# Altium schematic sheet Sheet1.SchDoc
size A3
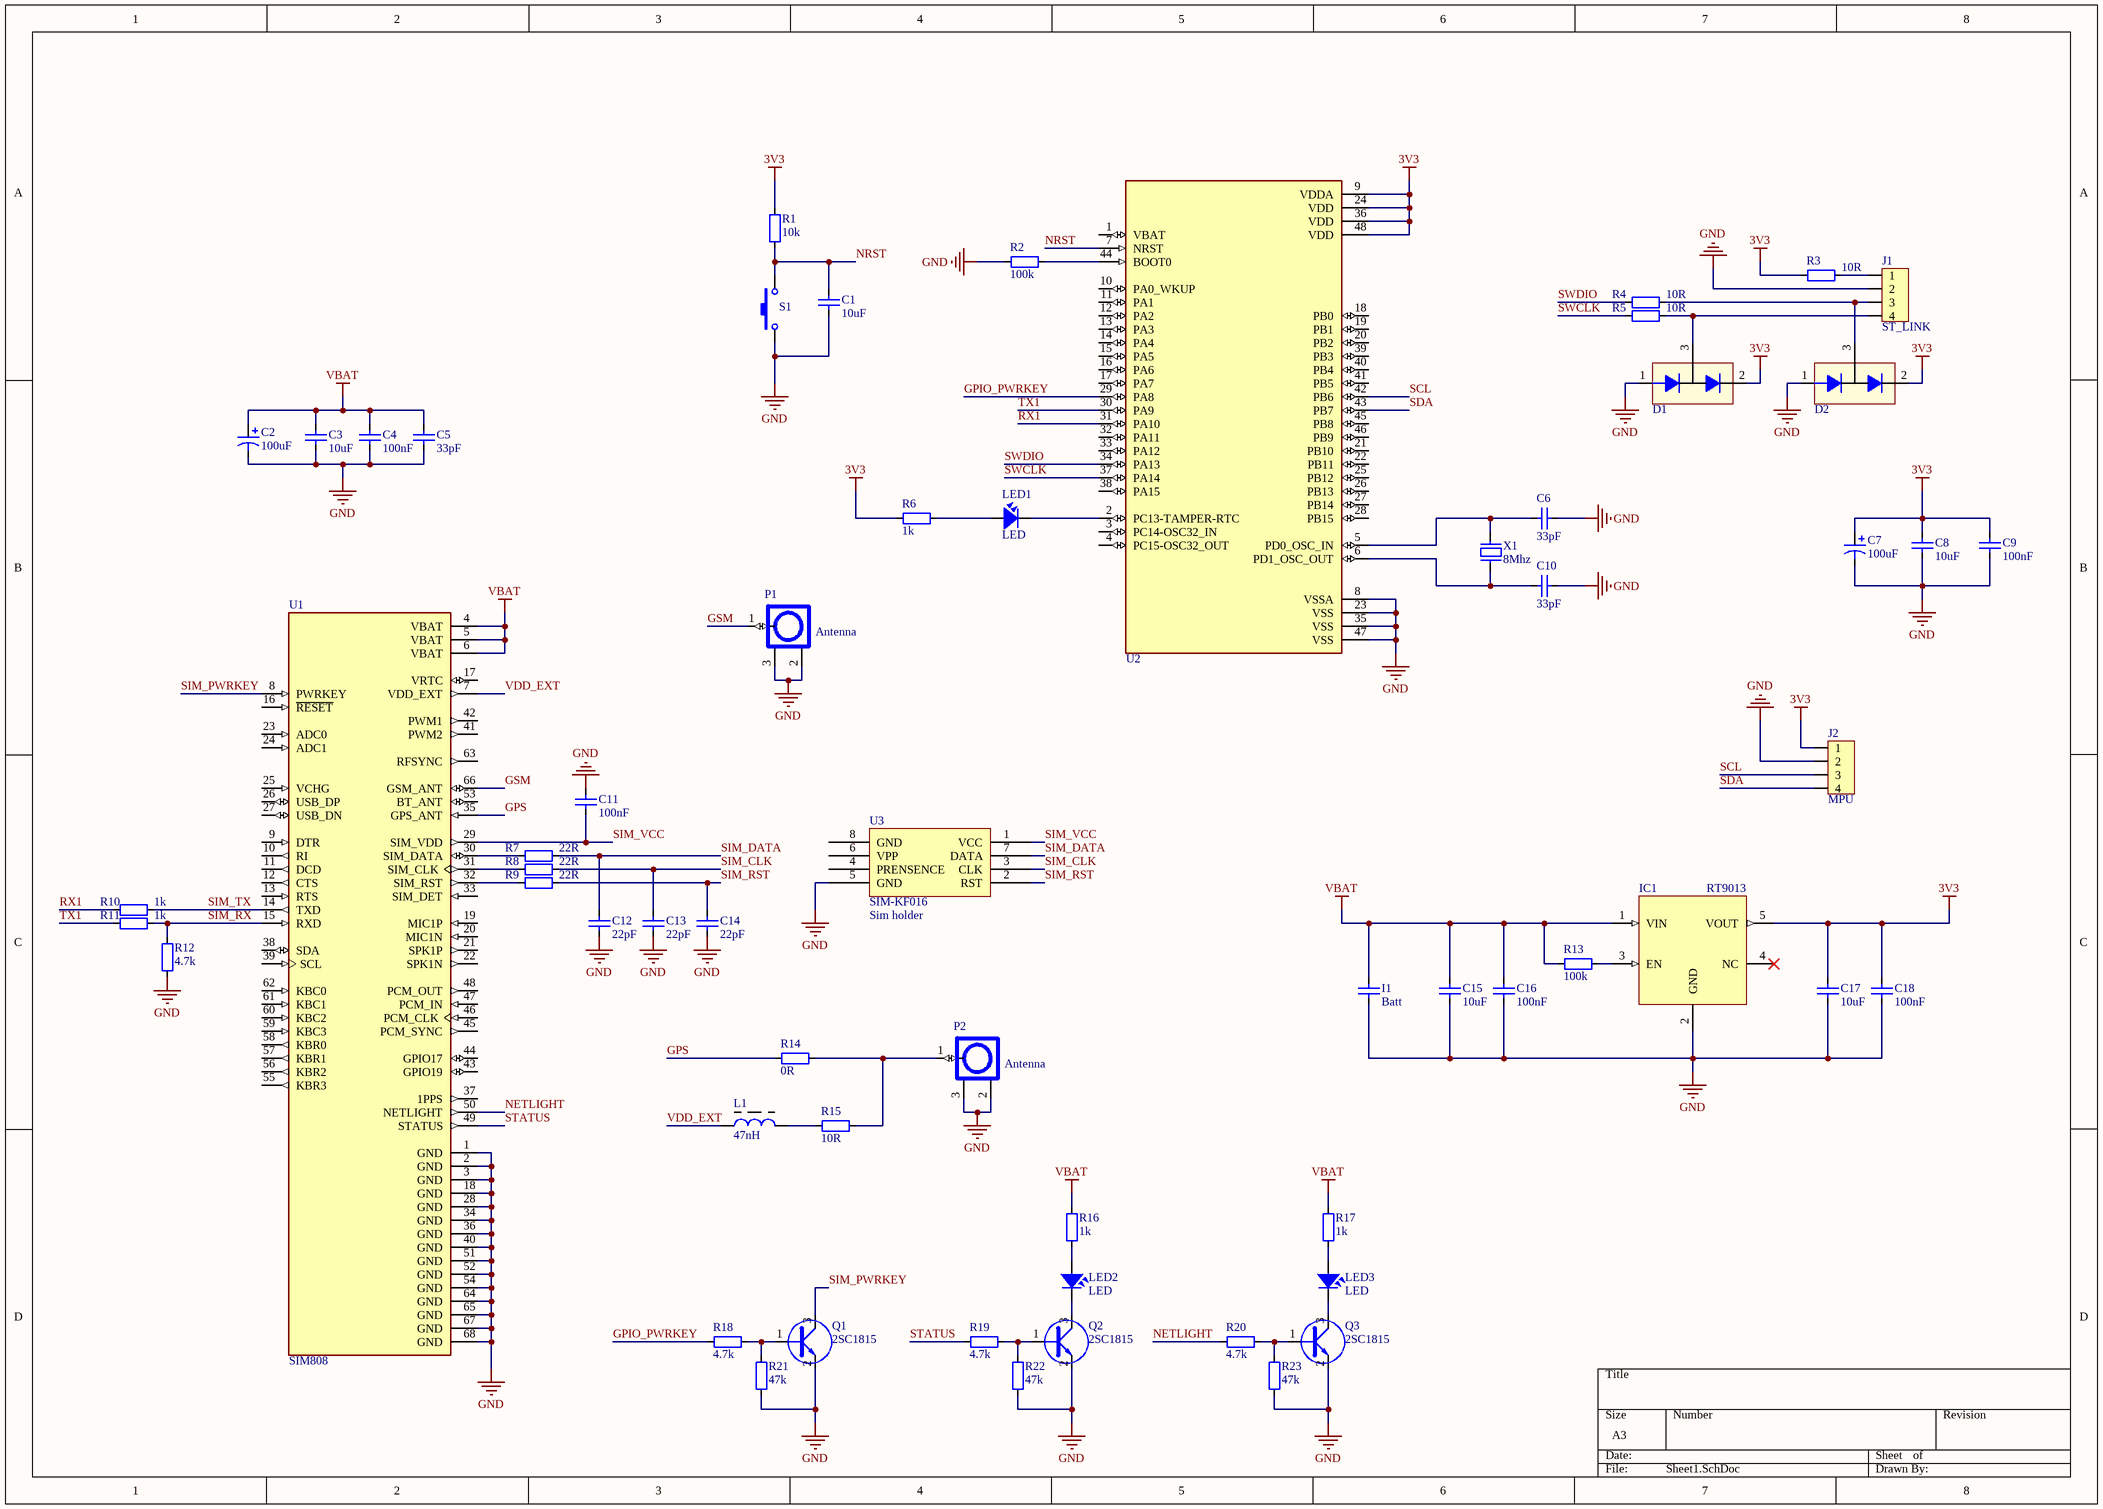
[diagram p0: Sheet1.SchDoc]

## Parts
C1  10uF  [CAP_0603]
C2  100uF  [CAP_7343]
C3  10uF  [CAP_0603]
C4  100nF  [CAP_0603]
C5  33pF  [CAP_0603]
C6  33pF  [CAP_0603]
C7  100uF  [CAP_7343]
C8  10uF  [CAP_0603]
C9  100nF  [CAP_0603]
C10  33pF  [CAP_0603]
C11  100nF  [CAP_0603]
C12  22pF  [CAP_0603]
C13  22pF  [CAP_0603]
C14  22pF  [CAP_0603]
C15  10uF  [CAP_0603]
C16  100nF  [CAP_0603]
C17  10uF  [CAP_0603]
C18  100nF  [CAP_0603]
D1  DIODE-BAV99  [SOT23]  (value not drawn)
D2  DIODE-BAV99  [SOT23]  (value not drawn)
I1  Batt  [CAP_3216]
IC1  RT9013  [SOT23-5]
J1  ST_LINK  [JP4-D1T]
J2  MPU  [JP4-D1T]
L1  47nH  [L-0805]
LED1  LED  [LED-0805-Orange]
LED2  LED  [LED-0805-Yellow]
LED3  LED  [LED-0805-Red]
P1  Antenna  [IPXS]
P2  Antenna  [IPXS]
Q1  2SC1815  [SOT23D]
Q2  2SC1815  [SOT23D]
Q3  2SC1815  [SOT23D]
R1  10k  [RES-SMD-0603]
R2  100k  [RES-SMD-0603]
R3  10R  [RES-SMD-0603]
R4  10R  [RES-SMD-0603]
R5  10R  [RES-SMD-0603]
R6  1k  [RES-SMD-0603]
R7  22R  [RES-SMD-0603]
R8  22R  [RES-SMD-0603]
R9  22R  [RES-SMD-0603]
R10  1k  [RES-SMD-0603]
R11  1k  [RES-SMD-0603]
R12  4.7k  [RES-SMD-0603]
R13  100k  [RES-SMD-0603]
R14  0R  [RES-SMD-0805]
R15  10R  [RES-SMD-0805]
R16  1k  [RES-SMD-0603]
R17  1k  [RES-SMD-0603]
R18  4.7k  [RES-SMD-0603]
R19  4.7k  [RES-SMD-0603]
R20  4.7k  [RES-SMD-0603]
R21  47k  [RES-SMD-0603]
R22  47k  [RES-SMD-0603]
R23  47k  [RES-SMD-0603]
S1  SW-SMD  [SW 3x2x4]  (value not drawn)
U1  SIM808  [XCVR_SIM808]
U2  STM32  [LQFP 48]  (value not drawn)
U3  SIM-KF016  value Sim holder  [Sim Socket]
X1  8Mhz  [XTAL 5032 SMD]

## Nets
3V3: C7.1 C8.2 C9.2 C17.2 C18.2 D1.2 D2.2 IC1.5(VOUT) J2.1 R1.2 R3.1 R6.1 U2.9(VDDA) U2.24(VDD) U2.36(VDD) U2.48(VDD)
GND: C1.1 C2.2 C3.1 C4.1 C5.1 C6.2 C7.2 C8.1 C9.1 C10.2 C11.1 C12.2 C13.2 C14.2 C15.1 C16.1 C17.1 C18.1 D1.1 D2.1 I1.1 IC1.2(GND) J1.2 J2.2 P1.2 P1.3 P2.2 P2.3 Q1.2(E) Q2.2(E) Q3.2(E) R2.2 R12.2 R21.1 R22.1 R23.1 S1.1 U1.1(GND) U1.2(GND) U1.3(GND) U1.18(GND) U1.28(GND) U1.34(GND) U1.36(GND) U1.40(GND) U1.51(GND) U1.52(GND) U1.54(GND) U1.64(GND) U1.65(GND) U1.67(GND) U1.68(GND) U2.8(VSSA) U2.23(VSS) U2.35(VSS) U2.47(VSS) U3.5(GND)
VBAT: C2.1 C3.2 C4.2 C5.2 C15.2 C16.2 I1.2 IC1.1(VIN) R13.2 R16.2 R17.2 U1.4(VBAT) U1.5(VBAT) U1.6(VBAT)
GPIO_PWRKEY: R18.1 U2.29(PA8)
GPS: R14.1 U1.35(GPS_ANT)
GSM: P1.1 U1.66(GSM_ANT)
NETLIGHT: R20.1 U1.50(NETLIGHT)
NRST: C1.2 R1.1 S1.2 U2.7(NRST)
RX1: R10.2 U2.31(PA10)
SCL: J2.3 U2.42(PB6)
SDA: J2.4 U2.43(PB7)
SIM_CLK: C13.1 R8.1 U3.3(CLK)
SIM_DATA: C12.1 R7.1 U3.7(DATA)
SIM_PWRKEY: Q1.3(C) U1.8(PWRKEY)
SIM_RST: C14.1 R9.1 U3.2(RST)
SIM_RX: R11.1 R12.1 U1.15(RXD)
SIM_TX: R10.1 U1.14(TXD)
SIM_VCC: C11.2 U1.29(SIM_VDD) U3.1(VCC)
STATUS: R19.1 U1.49(STATUS)
SWCLK: R5.1 U2.37(PA14)
SWDIO: R4.1 U2.34(PA13)
TX1: R11.2 U2.30(PA9)
VDD_EXT: L1.1 U1.7(VDD_EXT)
NetC6_1: C6.1 U2.5(PD0_OSC_IN) X1.2
NetC10_1: C10.1 U2.6(PD1_OSC_OUT) X1.1
NetD1_3: D1.3 J1.4 R5.2
NetD2_3: D2.3 J1.3 R4.2
NetIC1_3: IC1.3(EN) R13.1
NetJ1_1: J1.1 R3.2
NetL1_2: L1.2 R15.2
NetLED1_1: LED1.1 R6.2
NetLED1_2: LED1.2 U2.2(PC13-TAMPER-RTC)
NetLED2_1: LED2.1 R16.1
NetLED2_2: LED2.2 Q2.3(C)
NetLED3_1: LED3.1 R17.1
NetLED3_2: LED3.2 Q3.3(C)
NetP2_1: P2.1 R14.2 R15.1
NetQ1_1: Q1.1(B) R18.2 R21.2
NetQ2_1: Q2.1(B) R19.2 R22.2
NetQ3_1: Q3.1(B) R20.2 R23.2
NetR2_1: R2.1 U2.44(BOOT0)
NetR7_2: R7.2 U1.30(SIM_DATA)
NetR8_2: R8.2 U1.31(SIM_CLK)
NetR9_2: R9.2 U1.32(SIM_RST)

Not connected (* = marked no-connect by the designer): IC1 4(NC)*; U1 9(DTR) 10(RI) 11(DCD) 12(CTS) 13(RTS) 16(~{RESET}) 17(VRTC) 19(MIC1P) 20(MIC1N) 21(SPK1P) 22(SPK1N) 23(ADC0) 24(ADC1) 25(VCHG) 26(USB_DP) 27(USB_DN) 33(SIM_DET) 37(1PPS) 38(SDA) 39(SCL) 41(PWM2) 42(PWM1) 43(GPIO19) 44(GPIO17) 45(PCM_SYNC) 46(PCM_CLK) 47(PCM_IN) 48(PCM_OUT) 53(BT_ANT) 55(KBR3) 56(KBR2) 57(KBR1) 58(KBR0) 59(KBC3) 60(KBC2) 61(KBC1) 62(KBC0) 63(RFSYNC); U2 1(VBAT) 3(PC14-OSC32_IN) 4(PC15-OSC32_OUT) 10(PA0_WKUP) 11(PA1) 12(PA2) 13(PA3) 14(PA4) 15(PA5) 16(PA6) 17(PA7) 18(PB0) 19(PB1) 20(PB2) 21(PB10) 22(PB11) 25(PB12) 26(PB13) 27(PB14) 28(PB15) 32(PA11) 33(PA12) 38(PA15) 39(PB3) 40(PB4) 41(PB5) 45(PB8) 46(PB9); U3 4(PRENSENCE) 6(VPP) 8(GND)

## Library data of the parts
C1 C3-C6 C8-C18 = CapSMD: Capacitor; Value: 33p
C2 C7 = Cap Pol: Tantalum
D1 D2 = DIODE-BAV99: ZENER, SOT23,; Manufacturer: ON Semiconductor / Fairchild; Manufacturer Part Number: BAV99; .Creator: LeKhaLinh; Other Drawings: Diode Circuit; PCN Design/Specification: Mold Compound 12/Dec/2007; PCN Assembly/Origin: SOT23 Manufacturing Source 31/May2013 / Assembly Site Addition 20/Jul/2015; PCN Packaging: Binary Year Code Marking 15/Jan/2014; Diode Configuration: 1 Pair Series Connection; Diode Type: Standard; Voltage - DC Reverse (Vr) (Max): 70V; Current - Average Rectified (Io) (per Diode): 200mA; Voltage - Forward (Vf) (Max) @ If: 1.25V @ 150mA; Speed: Small Signal =; Reverse Recovery Time (trr): 6ns; Current - Reverse Leakage @ Vr: 2.5µA @ 70V; Online Catalog: Diode Array; Other Names: BAV99FSDKR
I1 = CapSMD: Pad; Value: 33p
IC1 = RT9013: RT9013-33GB IC REG LINEAR 3.3V 500mA SOT23-5
J1 J2 = Header4: Header IDC, 4 x 1 Pin Vertical 2.54mm Pitch (Non-Boxed, Male); Manufacturer: W¨¹rth Elektronik eiSos GmbH; partNo: 613002143121; ComponentLink1 Description: Manufacturer; ComponentLink2 Description: Datasheet; NoPins: 02
L1 = Inductor Ferit: Inductor; Value: 150 mH
LED1-LED3 = LED: LED Single colour Green and Red; Value: LED 3 ly Single Colour
P1 P2 = IPXSx66: Antenna GSM GPS
Q1-Q3 = 2SC1815: NPN 600mW, ECB; Value: C1815
R1-R23 = Resistor - SMD: Resistor; Manufacturer: Generic Components; Class: Passive
S1 = SW-SMD: Switch
U1 = SIM808: SIM808 GPS, GPRS/GSM RF Arduino Platform Evaluation Expansion Board; MF: Adafruit Industries
U2 = STM32F103C8T6: STM32 ARM-based 32-bit MCU with 64 Kbytes Flash, 64-pin LQFP, Industrial Temperature
U3 = Sim holder: SIM Card Holder KF-016
X1 = XT2: Crystal For all Crystal 2pin.; Value: 4Mhz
